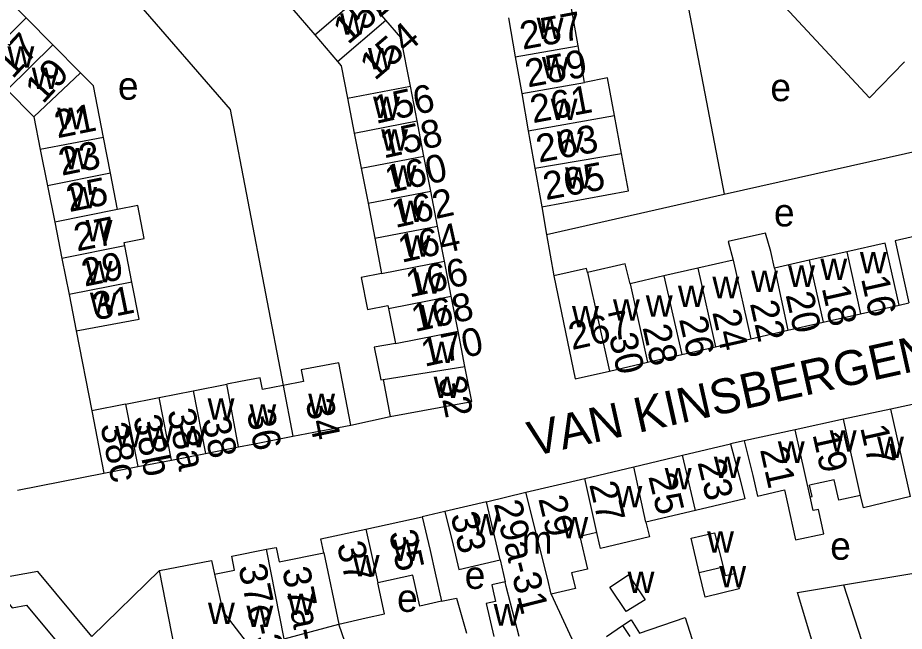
# Model space of a CAD drawing. Extents: x 159902 to 161769, y 383692 to 384875.
# Drawn here: x 160748.2 to 160875.8, y 384500.8 to 384589 of the extents above; entities that cross this region are included whole.
import ezdxf

# ---------------------------------------------------------------- set-up
doc = ezdxf.new("R2010")
doc.units = 0
for name, color, linetype in [('BLT_Basislijn', 7, 'Continuous'), ('BLT_Bebouwing', 7, 'Continuous'), ('BLT_Centroide', 7, 'Continuous'), ('BLT_Huisnummer', 7, 'Continuous'), ('BLT_Huisnummer_ tussenligend', 7, 'Continuous'), ('BLT_Huisnummer_reeks', 7, 'Continuous'), ('BLT_Onderverdeling_panden', 7, 'Continuous'), ('BLT_Straatnaam', 7, 'Continuous'), ('BLT_Vlakafsluiter', 7, 'Continuous')]:
    doc.layers.add(name, color=color, linetype=linetype)

msp = doc.modelspace()

# ---------------------------------------------------------------- linework, layer by layer
at = {"layer": 'BLT_Basislijn'}
for p, q in [((160849.88, 384563.61), (160886.59, 384571.89)), ((160824.3, 384557.83), (160849.88, 384563.61)), ((160823.61, 384561.79), (160824.3, 384557.83)), ((160824.3, 384557.83), (160825.34, 384551.88)), ((160875.02, 384547.68), (160876.45, 384548.01)), ((160756.63, 384543.96), (160758.87, 384532.46)), ((160796.15, 384530.42), (160801.81, 384531.65)), ((160852.74, 384528.16), (160850.79, 384527.7)), ((160748.21, 384521.03), (160760.62, 384523.48)), ((160809.67, 384517.98), (160806.42, 384517.22))]:
    msp.add_line(p, q, dxfattribs=at)
for points in [[(160776.05, 384669), (160843.06, 384599.13), (160849.88, 384563.61)], [(160765.29, 384591.35), (160778.77, 384575.83), (160786.4, 384536.1)], [(160758.87, 384500), (160751.1, 384509.34), (160700, 384500.18)]]:
    msp.add_lwpolyline(points, dxfattribs=at)
at = {"layer": 'BLT_Bebouwing'}
for p, q in [((160870.77, 384577.48), (160850.2, 384599.61)), ((160749.43, 384588.98), (160745.59, 384592.85)), ((160801.2, 384588.67), (160797.91, 384592.51)), ((160787.67, 384590.41), (160790.96, 384586.56)), ((160828.85, 384584.99), (160827.86, 384590.62)), ((160753.27, 384585.11), (160749.43, 384588.98)), ((160803.34, 384586.16), (160801.2, 384588.67)), ((160818.81, 384589.02), (160819.8, 384583.38)), ((160790.96, 384586.56), (160794.24, 384582.72)), ((160804.71, 384579.15), (160803.34, 384586.16)), ((160757.26, 384581.08), (160753.27, 384585.11)), ((160829.78, 384579.7), (160828.85, 384584.99)), ((160819.8, 384583.38), (160820.73, 384578.1)), ((160794.24, 384582.72), (160794.77, 384582.1)), ((160794.77, 384582.1), (160795.67, 384577.45)), ((160759.11, 384579.22), (160757.26, 384581.08)), ((160746.71, 384578.62), (160750.55, 384574.74)), ((160760.56, 384571.8), (160759.11, 384579.22)), ((160805.68, 384574.17), (160804.71, 384579.15)), ((160820.73, 384578.1), (160821.68, 384572.72)), ((160795.67, 384577.45), (160796.65, 384572.41)), ((160750.55, 384574.74), (160751.47, 384570.07)), ((160806.66, 384569.12), (160805.68, 384574.17)), ((160835.08, 384569.49), (160834.08, 384574.93)), ((160761.57, 384566.64), (160760.56, 384571.8)), ((160796.65, 384572.41), (160797.64, 384567.36)), ((160821.68, 384572.72), (160822.62, 384567.36)), ((160751.47, 384570.07), (160752.5, 384564.85)), ((160807.64, 384564.08), (160806.66, 384569.12)), ((160762.59, 384561.42), (160761.57, 384566.64)), ((160797.64, 384567.36), (160798.62, 384562.32)), ((160822.62, 384567.36), (160823.61, 384561.79)), ((160752.5, 384564.85), (160753.54, 384559.62)), ((160808.63, 384559.03), (160807.64, 384564.08)), ((160798.62, 384562.32), (160799.6, 384557.28)), ((160753.54, 384559.62), (160754.57, 384554.4)), ((160809.61, 384553.99), (160808.63, 384559.03)), ((160799.6, 384557.28), (160800.58, 384552.23)), ((160764.64, 384550.97), (160763.61, 384556.19)), ((160867.49, 384555.34), (160862.11, 384554.12)), ((160754.57, 384554.4), (160755.6, 384549.18)), ((160810.59, 384548.95), (160809.61, 384553.99)), ((160851.16, 384554.13), (160846.08, 384552.97)), ((160862.11, 384554.12), (160857.1, 384552.98)), ((160846.08, 384552.97), (160841.18, 384551.86)), ((160825.34, 384551.88), (160828.43, 384537.05)), ((160841.18, 384551.86), (160836.33, 384550.75)), ((160765.67, 384545.67), (160764.64, 384550.97)), ((160755.6, 384549.18), (160756.63, 384543.96)), ((160811.58, 384543.9), (160810.59, 384548.95)), ((160801.57, 384547.19), (160802.55, 384542.14)), ((160864.1, 384545.2), (160869.48, 384546.42)), ((160756.63, 384543.96), (160765.67, 384545.67)), ((160812.56, 384538.86), (160811.58, 384543.9)), ((160853.68, 384542.84), (160859.03, 384544.05)), ((160848.6, 384541.69), (160853.68, 384542.84)), ((160843.75, 384540.59), (160848.6, 384541.69)), ((160838.85, 384539.47), (160843.75, 384540.59)), ((160813.54, 384533.82), (160812.56, 384538.86)), ((160833.35, 384538.16), (160838.85, 384539.47)), ((160828.43, 384537.05), (160833.35, 384538.16)), ((160773.45, 384535.34), (160778.31, 384536.3)), ((160800.8, 384536.98), (160801.81, 384531.65)), ((160768.59, 384534.38), (160773.45, 384535.34)), ((160763.73, 384533.42), (160768.59, 384534.38)), ((160801.81, 384531.65), (160813.54, 384533.82)), ((160881.01, 384534.27), (160873.86, 384532.72)), ((160873.86, 384532.72), (160867.05, 384531.25)), ((160867.05, 384531.25), (160860.1, 384529.75)), ((160860.1, 384529.75), (160852.74, 384528.16)), ((160782.05, 384527.68), (160787.82, 384528.81)), ((160787.82, 384528.81), (160790.84, 384529.39)), ((160775.22, 384526.34), (160780, 384527.28)), ((160780, 384527.28), (160782.05, 384527.68)), ((160843.88, 384526.07), (160850.79, 384527.7)), ((160770.36, 384525.39), (160775.22, 384526.34)), ((160836.85, 384524.41), (160843.88, 384526.07)), ((160765.5, 384524.44), (160770.36, 384525.39)), ((160829.82, 384522.74), (160836.85, 384524.41)), ((160821.33, 384520.74), (160829.82, 384522.74)), ((160815.65, 384519.39), (160821.33, 384520.74)), ((160815.65, 384519.39), (160809.67, 384517.98)), ((160845.74, 384518.14), (160838.58, 384516.43)), ((160798.32, 384515.46), (160806.42, 384517.22)), ((160792.26, 384512.03), (160791.83, 384514.03)), ((160835.74, 384503.62), (160833.43, 384507.11)), ((160824.99, 384506.1), (160829.02, 384497.37)), ((160794.41, 384501.77), (160798.36, 384502.69)), ((160832.91, 384500), (160835.25, 384501.58)), ((160835.25, 384501.58), (160836.49, 384502.42))]:
    msp.add_line(p, q, dxfattribs=at)
for points in [[(160875.82, 384582.68), (160870.77, 384577.48)], [(160834.08, 384574.93), (160833.07, 384580.37), (160829.78, 384579.7)], [(160823.61, 384561.79), (160836.08, 384564.11), (160835.08, 384569.49)], [(160763.61, 384556.19), (160763.52, 384556.69), (160766.42, 384557.25), (160765.52, 384562), (160762.59, 384561.42)], [(160857.1, 384552.98), (160856.56, 384555.36), (160855.83, 384558.04), (160850.44, 384556.82), (160851.16, 384554.13)], [(160879.71, 384558.11), (160874.46, 384556.92), (160876.45, 384548.01)], [(160875.02, 384547.68), (160873.04, 384556.6), (160867.49, 384555.34)], [(160830.19, 384552.36), (160830.06, 384552.95), (160825.34, 384551.88)], [(160836.33, 384550.75), (160835.64, 384553.62), (160830.19, 384552.36)], [(160800.58, 384552.23), (160797.62, 384551.64), (160798.55, 384547.04), (160801.48, 384547.61), (160801.57, 384547.19)], [(160869.48, 384546.42), (160875.02, 384547.68)], [(160859.03, 384544.05), (160864.1, 384545.2)], [(160802.55, 384542.14), (160799.51, 384541.61), (160800.44, 384536.91), (160800.8, 384536.98)], [(160796.15, 384530.42), (160794.4, 384539.39), (160789.02, 384538.36)], [(160786.4, 384536.1), (160783.45, 384535.53), (160783.12, 384537.22), (160780.25, 384536.67)], [(160789.02, 384538.36), (160789.35, 384536.67), (160786.4, 384536.1)], [(160780.25, 384536.67), (160778.31, 384536.3)], [(160763.73, 384533.42), (160758.87, 384532.46)], [(160758.87, 384532.46), (160760.62, 384523.48)], [(160790.84, 384529.39), (160796.15, 384530.42)], [(160850.79, 384527.7), (160852.17, 384522.54), (160852.82, 384519.82), (160845.74, 384518.14)], [(160852.74, 384528.16), (160854.01, 384523.16), (160854.67, 384520.21), (160858.55, 384521.08), (160858.94, 384519.36), (160860.15, 384513.89), (160864.19, 384514.79), (160863.42, 384518.27), (160862.69, 384518.11), (160862.25, 384520.09)], [(160760.62, 384523.48), (160765.5, 384524.44)], [(160869.5, 384520.27), (160866.34, 384519.62), (160865.68, 384522.56), (160862.14, 384521.77)], [(160862.25, 384520.09), (160862.51, 384520.15), (160862.14, 384521.77)], [(160876.67, 384520.14), (160869.89, 384518.53), (160869.5, 384520.27)], [(160806.42, 384517.22), (160807.55, 384512.35), (160808.28, 384509.1), (160809.19, 384505.06)], [(160809.67, 384517.98), (160810.89, 384513.15), (160811.71, 384509.65), (160817.61, 384511.04)], [(160791.83, 384514.03), (160798.32, 384515.46)], [(160838.58, 384516.43), (160839.12, 384514.35), (160832.07, 384512.67), (160831.98, 384513.04), (160831.53, 384514.95)], [(160829.09, 384514.37), (160830.2, 384509.71), (160827.92, 384509.16), (160828.45, 384506.92), (160824.99, 384506.1)], [(160831.53, 384514.95), (160829.09, 384514.37)], [(160846.28, 384509.23), (160845.12, 384514.14), (160848.45, 384514.93), (160849.71, 384510.01)], [(160779.02, 384511.57), (160784.03, 384512.55)], [(160784.03, 384512.55), (160785.42, 384512.82)], [(160785.42, 384512.82), (160785.82, 384510.76), (160792.26, 384512.03)], [(160768.62, 384509.5), (160776.12, 384510.95), (160776.51, 384508.96)], [(160776.51, 384508.96), (160779.42, 384509.53), (160779.02, 384511.57)], [(160817.61, 384511.04), (160818.34, 384507.85)], [(160867.05, 384507.42), (160876.87, 384509.04), (160887.45, 384511.42)], [(160775.61, 384492.48), (160770.82, 384498.23), (160768.62, 384509.5)], [(160849.71, 384510.01), (160850.02, 384508.76), (160851.38, 384509.06), (160852.02, 384506.86), (160847.13, 384505.68), (160846.28, 384509.23)], [(160809.19, 384505.06), (160806.08, 384504.38), (160805.09, 384508.83), (160800.01, 384507.7)], [(160818.34, 384507.85), (160816.44, 384507.41), (160816.64, 384506.53)], [(160833.43, 384507.11), (160836.11, 384508.88), (160838.52, 384505.28), (160835.74, 384503.62)], [(160798.36, 384502.69), (160800.97, 384503.26), (160800.01, 384507.7)], [(160816.64, 384506.53), (160816.98, 384505.05), (160815.63, 384504.74), (160816.7, 384500)], [(160862.48, 384499.49), (160860.41, 384506.33), (160867.05, 384507.42)], [(160733.41, 384501.57), (160743.97, 384503.51), (160746.35, 384505.48), (160747.44, 384504.14), (160749.48, 384504.51), (160755.21, 384497.65), (160753.83, 384496.49), (160755.27, 384494.77)], [(160809.19, 384505.06), (160811.36, 384505.53), (160812.79, 384500.48)], [(160836.49, 384502.42), (160837.69, 384500.5), (160844.24, 384502.72)], [(160844.24, 384502.72), (160846.87, 384494.44), (160862.48, 384499.49)], [(160797.1, 384494.01), (160794.41, 384501.77)]]:
    msp.add_lwpolyline(points, dxfattribs=at)
at = {"layer": 'BLT_Onderverdeling_panden'}
for p, q in [((160790.96, 384586.56), (160797.91, 384592.51)), ((160749.43, 384588.98), (160742.88, 384582.5)), ((160794.24, 384582.72), (160801.2, 384588.67)), ((160753.27, 384585.11), (160746.71, 384578.62)), ((160819.8, 384583.38), (160828.85, 384584.99)), ((160757.26, 384581.08), (160750.55, 384574.74)), ((160820.73, 384578.1), (160829.78, 384579.7)), ((160795.67, 384577.45), (160804.71, 384579.15)), ((160796.65, 384572.41), (160805.68, 384574.17)), ((160821.68, 384572.72), (160834.08, 384574.93)), ((160760.56, 384571.8), (160751.47, 384570.07)), ((160797.64, 384567.36), (160806.66, 384569.12)), ((160822.62, 384567.36), (160835.08, 384569.49)), ((160761.57, 384566.64), (160752.5, 384564.85)), ((160798.62, 384562.32), (160807.64, 384564.08)), ((160762.59, 384561.42), (160753.54, 384559.62)), ((160799.6, 384557.28), (160808.63, 384559.03)), ((160763.61, 384556.19), (160754.57, 384554.4)), ((160867.49, 384555.34), (160869.48, 384546.42)), ((160800.58, 384552.23), (160809.61, 384553.99)), ((160851.16, 384554.13), (160853.68, 384542.84)), ((160862.11, 384554.12), (160864.1, 384545.2)), ((160846.08, 384552.97), (160848.6, 384541.69)), ((160857.1, 384552.98), (160859.03, 384544.05)), ((160830.19, 384552.36), (160833.35, 384538.16)), ((160841.18, 384551.86), (160843.75, 384540.59)), ((160764.64, 384550.97), (160755.6, 384549.18)), ((160836.33, 384550.75), (160838.85, 384539.47)), ((160801.57, 384547.19), (160810.59, 384548.95)), ((160802.55, 384542.14), (160811.58, 384543.9)), ((160800.8, 384536.98), (160812.56, 384538.86)), ((160780, 384527.28), (160778.31, 384536.3)), ((160786.4, 384536.1), (160787.82, 384528.81)), ((160773.45, 384535.34), (160775.22, 384526.34)), ((160763.73, 384533.42), (160765.5, 384524.44)), ((160770.36, 384525.39), (160768.59, 384534.38)), ((160876.67, 384520.14), (160873.86, 384532.72)), ((160869.5, 384520.27), (160867.05, 384531.25)), ((160862.25, 384520.09), (160860.1, 384529.75)), ((160845.74, 384518.14), (160843.88, 384526.07)), ((160838.58, 384516.43), (160836.85, 384524.41)), ((160831.53, 384514.95), (160829.82, 384522.74)), ((160824.44, 384508.39), (160821.33, 384520.74)), ((160817.61, 384511.04), (160815.65, 384519.39)), ((160798.32, 384515.46), (160800.01, 384507.7)), ((160786.57, 384499.65), (160784.03, 384512.55)), ((160846.28, 384509.23), (160849.71, 384510.01)), ((160776.51, 384508.96), (160777.73, 384503.59)), ((160818.51, 384507.17), (160818.34, 384507.85)), ((160820.36, 384500), (160818.51, 384507.17)), ((160867.05, 384507.42), (160870.76, 384495.85)), ((160777.73, 384503.59), (160782.07, 384497.98)), ((160786.57, 384499.65), (160794.41, 384501.77)), ((160835.25, 384501.58), (160836.29, 384500))]:
    msp.add_line(p, q, dxfattribs=at)
for points in [[(160792.26, 384512.03), (160794.41, 384501.77)], [(160824.99, 384506.1), (160824.44, 384508.39)]]:
    msp.add_lwpolyline(points, dxfattribs=at)
at = {"layer": 'BLT_Vlakafsluiter'}
msp.add_line((160758.87, 384500), (160768.62, 384509.5), dxfattribs=at)

# ---------------------------------------------------------------- texts
at = {"layer": 'BLT_Centroide'}
for s, p in [('w', (160794.59, 384586.57)), ('w', (160822.88, 384585.93)), ('w', (160746.74, 384581.84)), ('w', (160798.61, 384581.59)), ('w', (160823.64, 384580.28)), ('w', (160750.24, 384578.75)), ('e', (160762.63, 384577.22)), ('e', (160856.51, 384577.01)), ('w', (160799.35, 384574.57)), ('w', (160824.9, 384574.31)), ('w', (160753.89, 384572.98)), ('w', (160800.51, 384569.88)), ('w', (160825.78, 384569.6)), ('w', (160754.87, 384567.21)), ('w', (160801.74, 384564.72)), ('w', (160826.97, 384564.41)), ('w', (160755.76, 384561.6)), ('w', (160802.81, 384559.61)), ('e', (160857.02, 384558.99)), ('w', (160757.99, 384556.85)), ('w', (160803.74, 384554.63)), ('w', (160869.39, 384552.24)), ('w', (160757.99, 384550.95)), ('w', (160863.7, 384551.29)), ('w', (160853.74, 384549.56)), ('w', (160859.06, 384550.3)), ('w', (160805.38, 384549.3)), ('w', (160848.17, 384548.67)), ('w', (160843.21, 384547.42)), ('w', (160758.6, 384546.39)), ('w', (160838.59, 384545.99)), ('w', (160806.17, 384544.6)), ('w', (160827.97, 384544.46)), ('w', (160833.86, 384545.45)), ('w', (160807.28, 384539.35)), ('w', (160808.06, 384534.3)), ('w', (160790.01, 384531.87)), ('w', (160775.54, 384531.19)), ('w', (160781.55, 384530.35)), ('w', (160762.21, 384527.21)), ('w', (160766.71, 384527.21)), ('w', (160771.47, 384527.21)), ('w', (160865.05, 384526.58)), ('w', (160871.86, 384525.66)), ('w', (160857.58, 384524.98)), ('w', (160848.38, 384522.78)), ('w', (160841.31, 384521.16)), ('w', (160834.22, 384518.59)), ('w', (160813.67, 384514.53)), ('w', (160826.44, 384514.14)), ('m', (160820.72, 384511.94)), ('w', (160847.41, 384512.08)), ('w', (160802.19, 384510.88)), ('e', (160865.12, 384511.04)), ('w', (160796.42, 384508.67)), ('e', (160812.53, 384506.85)), ('w', (160835.97, 384506.27)), ('w', (160849.16, 384507.08)), ('e', (160802.8, 384503.54)), ('w', (160787.06, 384503.08)), ('w', (160775.59, 384501.78)), ('w', (160781.12, 384501.37)), ('w', (160816.7, 384501.58))]:
    msp.add_text(s, height=4, dxfattribs=at).set_placement(p)
at = {"layer": 'BLT_Huisnummer'}
for s, rotation, p in [('152', 40.3931, (160795.73, 384585.05)), ('257', 10.5428, (160820.87, 384584.4)), ('154', 40.3931, (160799.59, 384579.87)), ('19', 47.3931, (160751.84, 384576.49)), ('156', 12.5428, (160799.76, 384573.73)), ('261', 10.5428, (160822.34, 384573.83)), ('21', 11.3931, (160753.93, 384571.66)), ('160', 12.5428, (160801.56, 384563.73)), ('265', 10.5428, (160824.19, 384562.76)), ('25', 11.3931, (160755.64, 384561.04)), ('164', 12.5428, (160803.45, 384553.75)), ('29', 11.3931, (160757.83, 384550.31)), ('16', 282.5733, (160869.53, 384551.51)), ('31', 11.3931, (160759.39, 384545.45)), ('168', 12.5428, (160805.35, 384543.78)), ('20', 282.5733, (160858.68, 384549.16)), ('267', 12.5733, (160827.96, 384541.19)), ('24', 282.5733, (160848.13, 384546.66)), ('28', 282.5733, (160838.1, 384544.48)), ('170', 12.5428, (160806.75, 384538.78)), ('30', 282.5733, (160833.26, 384543.25)), ('32', 281.3931, (160808.68, 384537.07)), ('34', 281.3931, (160789.61, 384533.85)), ('38a', 281.3931, (160769.71, 384532.42)), ('36', 281.3931, (160781.15, 384532.32)), ('38c', 281.3931, (160760.08, 384530.4)), ('38b', 281.3931, (160764.81, 384531.52)), ('38', 281.3931, (160774.75, 384531.21)), ('19', 282.5648, (160862.55, 384529.09)), ('23', 283.3799, (160846, 384525.07)), ('27', 283.3283, (160830.43, 384521.87)), ('35', 282.2737, (160801.61, 384514.93)), ('37', 283.9195, (160794.09, 384513.2))]:
    msp.add_text(s, height=4, rotation=rotation, dxfattribs=at).set_placement(p)
at = {"layer": 'BLT_Huisnummer_ tussenligend'}
for s, rotation, p in [('17', 47.3931, (160747.48, 384580.09)), ('259', 10.5428, (160821.61, 384578.97)), ('158', 12.5428, (160800.88, 384568.75)), ('263', 10.5428, (160823.2, 384568.15)), ('23', 11.3931, (160754.54, 384566.27)), ('162', 12.5428, (160802.54, 384558.75)), ('27', 11.3931, (160756.74, 384555.38)), ('166', 12.5428, (160804.58, 384548.75)), ('18', 282.5733, (160863.88, 384550.16)), ('22', 282.5733, (160853.55, 384547.92)), ('26', 282.5733, (160843.35, 384545.67)), ('17', 282.5733, (160869.42, 384530.08)), ('21', 282.5648, (160855, 384526.9)), ('25', 283.3799, (160838.93, 384523.04)), ('29', 283.3283, (160823.1, 384519.84)), ('33', 283.321, (160810.47, 384517.46))]:
    msp.add_text(s, height=4, rotation=rotation, dxfattribs=at).set_placement(p)
at = {"layer": 'BLT_Huisnummer_reeks'}
for s, rotation, p in [('29a-31', 284.1369, (160816.7, 384519.12)), ('37c-39-b', 282.1496, (160779.93, 384510.04)), ('37a-b', 281.1509, (160786.25, 384509.66))]:
    msp.add_text(s, height=4, rotation=rotation, dxfattribs=at).set_placement(p)
at = {"layer": 'BLT_Straatnaam'}
msp.add_text('VAN KINSBERGENSTRAAT', height=5, rotation=12.5698, dxfattribs=at).set_placement((160822.26, 384525.88))

doc.saveas('drawing.dxf')
